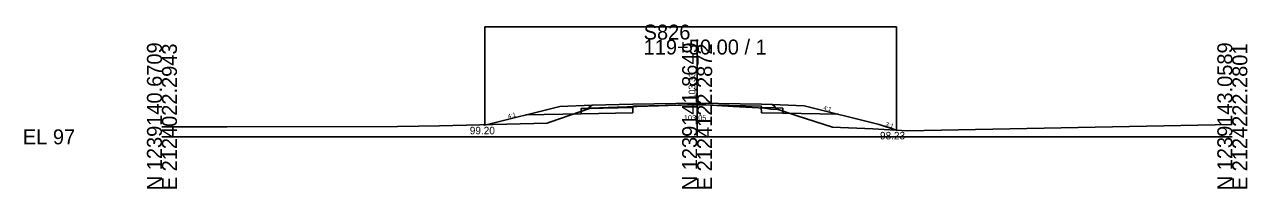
# Model space of a CAD drawing. Extents: x 2119282 to 2119710, y 1215030 to 1220057.
# Drawn here: x 2119381.9 to 2119610.4, y 1218030.1 to 1218060.9 of the extents above; entities that cross this region are included whole.
import ezdxf

# ---------------------------------------------------------------- set-up
doc = ezdxf.new("R2010")
doc.units = 0
for name, color, linetype in [('XS_CELL', 7, 'Continuous'), ('XS_M_DITCH', 7, 'Continuous'), ('XS_P_FINISHED_GRADE', 7, 'Continuous'), ('XS_P_FINISHED_GRADE_ELEV_TX', 7, 'Continuous'), ('XS_P_SUBGRADE_GRANULAR', 7, 'Continuous'), ('XS_P_SUBGRADE_PAVEMENT', 7, 'Continuous'), ('XS_P_TX_DCH', 7, 'Continuous'), ('XS_P_TX_FS_BS', 7, 'Continuous'), ('XS_X_GROUND', 7, 'Continuous'), ('XS_X_GROUND_TX', 7, 'Continuous')]:
    doc.layers.add(name, color=color, linetype=linetype)

msp = doc.modelspace()

# ---------------------------------------------------------------- linework, layer by layer
at = {"layer": 'XS_CELL'}
for p, q in [((2119507.6, 1218039.8), (2119507.6, 1218058.02)), ((2119407.6, 1218039.8), (2119507.6, 1218039.8)), ((2119507.6, 1218039.8), (2119607.6, 1218039.8))]:
    msp.add_line(p, q, dxfattribs=at)
at = {"layer": 'XS_M_DITCH'}
for p, q in [((2119467.96, 1218042), (2119467.96, 1218060.42)), ((2119467.96, 1218060.42), (2119544.83, 1218060.42)), ((2119544.83, 1218041.04), (2119544.83, 1218060.42))]:
    msp.add_line(p, q, dxfattribs=at)
at = {"layer": 'XS_P_FINISHED_GRADE'}
for p, q in [((2119481.96, 1218045.5), (2119467.96, 1218042)), ((2119487.96, 1218045.74), (2119481.96, 1218045.5)), ((2119495.6, 1218045.89), (2119487.96, 1218045.74)), ((2119507.6, 1218046.13), (2119495.6, 1218045.89)), ((2119507.6, 1218046.13), (2119519.6, 1218045.89)), ((2119519.6, 1218045.89), (2119521.6, 1218045.85)), ((2119521.6, 1218045.85), (2119527.6, 1218045.61)), ((2119527.6, 1218045.61), (2119541.6, 1218042.11)), ((2119467.96, 1218042), (2119467.71, 1218042.08)), ((2119541.6, 1218042.11), (2119544.83, 1218041.04))]:
    msp.add_line(p, q, dxfattribs=at)
at = {"layer": 'XS_P_SUBGRADE_GRANULAR'}
for p, q in [((2119487.31, 1218045.14), (2119485.96, 1218045.09)), ((2119485.96, 1218044.12), (2119485.96, 1218045.09)), ((2119495.6, 1218044.31), (2119495.61, 1218045.31)), ((2119519.6, 1218044.31), (2119519.59, 1218045.31)), ((2119522.26, 1218045.26), (2119523.6, 1218045.2)), ((2119523.6, 1218044.23), (2119523.6, 1218045.2)), ((2119485.96, 1218044.12), (2119475.6, 1218043.91)), ((2119495.6, 1218044.31), (2119485.96, 1218044.12)), ((2119519.6, 1218044.31), (2119523.6, 1218044.23)), ((2119523.6, 1218044.23), (2119533.97, 1218044.02))]:
    msp.add_line(p, q, dxfattribs=at)
at = {"layer": 'XS_P_SUBGRADE_PAVEMENT'}
for p, q in [((2119487.46, 1218045.4), (2119487.31, 1218045.14)), ((2119495.61, 1218045.31), (2119487.31, 1218045.14)), ((2119487.96, 1218045.74), (2119487.46, 1218045.4)), ((2119507.6, 1218045.8), (2119495.61, 1218045.56)), ((2119495.61, 1218045.31), (2119495.61, 1218045.56)), ((2119507.6, 1218045.8), (2119519.6, 1218045.56)), ((2119519.59, 1218045.31), (2119519.6, 1218045.56)), ((2119519.59, 1218045.31), (2119522.26, 1218045.26)), ((2119521.6, 1218045.85), (2119522.11, 1218045.51)), ((2119522.11, 1218045.51), (2119522.26, 1218045.26))]:
    msp.add_line(p, q, dxfattribs=at)
at = {"layer": 'XS_X_GROUND'}
for p, q in [((2119480.06, 1218042.55), (2119487.67, 1218045.16)), ((2119487.67, 1218045.16), (2119492.68, 1218045.33)), ((2119492.68, 1218045.33), (2119496.36, 1218045.47)), ((2119496.36, 1218045.47), (2119500.35, 1218045.61)), ((2119500.35, 1218045.61), (2119507.6, 1218045.85)), ((2119507.6, 1218045.85), (2119508.21, 1218045.87)), ((2119508.21, 1218045.87), (2119514.34, 1218045.5)), ((2119514.34, 1218045.5), (2119520.24, 1218045.16)), ((2119520.24, 1218045.16), (2119521.34, 1218045.01)), ((2119521.34, 1218045.01), (2119522.73, 1218044.9)), ((2119522.73, 1218044.9), (2119526.3, 1218043.73)), ((2119459.44, 1218041.88), (2119479.6, 1218042.38)), ((2119479.6, 1218042.38), (2119480.06, 1218042.55)), ((2119526.3, 1218043.73), (2119532.89, 1218041.62)), ((2119407.6, 1218041.67), (2119419.76, 1218041.69)), ((2119419.76, 1218041.69), (2119451.59, 1218041.74)), ((2119451.59, 1218041.74), (2119459.44, 1218041.88)), ((2119532.89, 1218041.62), (2119540.44, 1218041.28)), ((2119540.44, 1218041.28), (2119546.86, 1218040.92)), ((2119546.86, 1218040.92), (2119607.6, 1218042.13))]:
    msp.add_line(p, q, dxfattribs=at)

# ---------------------------------------------------------------- texts
at = {"layer": 'XS_CELL'}
for s, p in [('S826', (2119497.6, 1218058.02)), ('119+50.00 / 1', (2119497.6, 1218055.22)), ('EL 97', (2119381.6, 1218038.4))]:
    msp.add_text(s, height=2.8, dxfattribs=at).set_placement(p)
for s, p in [('N 1239140.6709', (2119407.6, 1218029.8)), ('E 2124022.2943', (2119410.4, 1218029.8)), ('N 1239141.8649', (2119507.6, 1218029.8)), ('E 2124122.2872', (2119510.4, 1218029.8)), ('N 1239143.0589', (2119607.6, 1218029.8)), ('E 2124222.2801', (2119610.4, 1218029.8))]:
    msp.add_text(s, height=2.8, rotation=90, dxfattribs=at).set_placement(p)
at = {"layer": 'XS_P_FINISHED_GRADE_ELEV_TX'}
msp.add_text('103.33', height=1.25, rotation=90, dxfattribs=at).set_placement((2119507.26, 1218046.8))
at = {"layer": 'XS_P_TX_DCH'}
for s, p in [('99.20', (2119465.12, 1218040.28)), ('98.23', (2119541.77, 1218039.33))]:
    msp.add_text(s, height=1.4, dxfattribs=at).set_placement(p)
at = {"layer": 'XS_P_TX_FS_BS'}
for s, rotation, p in [('4:1', 345.9638, (2119531.11, 1218044.91)), ('4:1', 14.0362, (2119472.31, 1218043.24)), ('3:1', 341.5651, (2119542.71, 1218041.89))]:
    msp.add_text(s, height=0.8, rotation=rotation, dxfattribs=at).set_placement(p)
at = {"layer": 'XS_X_GROUND_TX'}
msp.add_text('103.05', height=1, dxfattribs=at).set_placement((2119505.11, 1218042.86))

doc.saveas('drawing.dxf')
